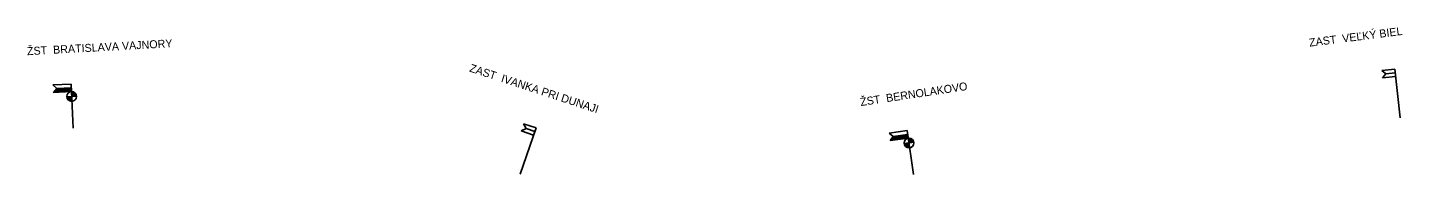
# Model space of a CAD drawing. Extents: x -566241 to -448637, y -1329577 to -1274522.
# Drawn here: x -566241 to -554213, y -1276346 to -1275058 of the extents above; entities that cross this region are included whole.
import ezdxf

# ---------------------------------------------------------------- set-up
doc = ezdxf.new("R2010")
doc.units = 0
doc.layers.add('DOPRAVNE', color=7, linetype='Continuous')
doc.layers.add('DOPRAVNE NAZOV', color=7, linetype='Continuous')

msp = doc.modelspace()

# ---------------------------------------------------------------- linework, layer by layer
at = {"layer": 'DOPRAVNE'}
for p, q in [((-554280, -1275422), (-554394, -1275435)), ((-554394, -1275435), (-554358, -1275464)), ((-554358, -1275464), (-554387, -1275500)), ((-554273, -1275488), (-554387, -1275500)), ((-554277, -1275455), (-554358, -1275464)), ((-554234, -1275848), (-554280, -1275422)), ((-565860, -1275553), (-566020, -1275561)), ((-566020, -1275561), (-565986, -1275593)), ((-565986, -1275593), (-566017, -1275627)), ((-565857, -1275619), (-566017, -1275627)), ((-566015, -1275627), (-565984, -1275592)), ((-566008, -1275627), (-565976, -1275592)), ((-566001, -1275626), (-565969, -1275592)), ((-565994, -1275626), (-565962, -1275591)), ((-565987, -1275626), (-565955, -1275591)), ((-565858, -1275586), (-565986, -1275593)), ((-565980, -1275625), (-565948, -1275591)), ((-565973, -1275625), (-565941, -1275590)), ((-565966, -1275625), (-565934, -1275590)), ((-565958, -1275624), (-565927, -1275590)), ((-565951, -1275624), (-565920, -1275589)), ((-565944, -1275624), (-565913, -1275589)), ((-565937, -1275623), (-565906, -1275589)), ((-565930, -1275623), (-565899, -1275588)), ((-565923, -1275623), (-565892, -1275588)), ((-565916, -1275622), (-565885, -1275588)), ((-565909, -1275622), (-565878, -1275587)), ((-565902, -1275622), (-565871, -1275587)), ((-565895, -1275621), (-565863, -1275587)), ((-565888, -1275621), (-565858, -1275588)), ((-565881, -1275621), (-565858, -1275596)), ((-565874, -1275620), (-565858, -1275603)), ((-565874, -1275620), (-565858, -1275603)), ((-565867, -1275620), (-565857, -1275610)), ((-565867, -1275620), (-565857, -1275610)), ((-565842, -1275941), (-565860, -1275553)), ((-565860, -1275620), (-565857, -1275617)), ((-565860, -1275620), (-565857, -1275617)), ((-565857, -1275624), (-565853, -1275619)), ((-565856, -1275631), (-565847, -1275620)), ((-565856, -1275638), (-565841, -1275622)), ((-565856, -1275645), (-565836, -1275624)), ((-565855, -1275652), (-565832, -1275626)), ((-565855, -1275659), (-565828, -1275629)), ((-565898, -1275664), (-565812, -1275660)), ((-565897, -1275669), (-565893, -1275664)), ((-565896, -1275675), (-565886, -1275664)), ((-565894, -1275680), (-565879, -1275664)), ((-565892, -1275685), (-565872, -1275663)), ((-565889, -1275689), (-565865, -1275663)), ((-565885, -1275693), (-565858, -1275663)), ((-565882, -1275696), (-565855, -1275666)), ((-565878, -1275699), (-565854, -1275673)), ((-565873, -1275701), (-565854, -1275680)), ((-565868, -1275703), (-565854, -1275687)), ((-565863, -1275705), (-565853, -1275694)), ((-565851, -1275662), (-565824, -1275632)), ((-565844, -1275662), (-565821, -1275636)), ((-565837, -1275662), (-565818, -1275640)), ((-565830, -1275661), (-565815, -1275645)), ((-565823, -1275661), (-565813, -1275651)), ((-561932, -1276343), (-561792, -1275938)), ((-561880, -1275943), (-561922, -1275963)), ((-561814, -1276001), (-561922, -1275963)), ((-561792, -1275938), (-561901, -1275901)), ((-561901, -1275901), (-561880, -1275943)), ((-561803, -1275970), (-561880, -1275943)), ((-558545, -1275961), (-558704, -1275984)), ((-558704, -1275984), (-558667, -1276012)), ((-558490, -1276346), (-558545, -1275961)), ((-558667, -1276012), (-558695, -1276049)), ((-558536, -1276026), (-558695, -1276049)), ((-558692, -1276049), (-558664, -1276012)), ((-558685, -1276048), (-558657, -1276011)), ((-558678, -1276047), (-558650, -1276010)), ((-558671, -1276046), (-558643, -1276009)), ((-558540, -1275994), (-558667, -1276012)), ((-558664, -1276045), (-558636, -1276008)), ((-558657, -1276044), (-558629, -1276007)), ((-558650, -1276043), (-558622, -1276006)), ((-558643, -1276042), (-558615, -1276005)), ((-558636, -1276041), (-558608, -1276004)), ((-558629, -1276040), (-558601, -1276003)), ((-558622, -1276039), (-558594, -1276002)), ((-558615, -1276038), (-558587, -1276001)), ((-558608, -1276037), (-558580, -1276000)), ((-558601, -1276036), (-558573, -1275998)), ((-558594, -1276035), (-558566, -1275997)), ((-558587, -1276034), (-558559, -1275996)), ((-558580, -1276033), (-558552, -1275995)), ((-558573, -1276032), (-558545, -1275994)), ((-558572, -1276075), (-558487, -1276063)), ((-558571, -1276079), (-558568, -1276075)), ((-558570, -1276085), (-558561, -1276074)), ((-558567, -1276090), (-558554, -1276073)), ((-558566, -1276031), (-558540, -1275996)), ((-558564, -1276095), (-558547, -1276072)), ((-558561, -1276099), (-558540, -1276071)), ((-558559, -1276030), (-558539, -1276003)), ((-558557, -1276102), (-558533, -1276070)), ((-558553, -1276105), (-558529, -1276073)), ((-558552, -1276029), (-558538, -1276010)), ((-558552, -1276029), (-558538, -1276010)), ((-558549, -1276108), (-558528, -1276080)), ((-558545, -1276028), (-558537, -1276017)), ((-558545, -1276028), (-558537, -1276017)), ((-558544, -1276110), (-558527, -1276087)), ((-558539, -1276111), (-558526, -1276094)), ((-558538, -1276027), (-558536, -1276024)), ((-558538, -1276027), (-558536, -1276024)), ((-558535, -1276031), (-558532, -1276026)), ((-558534, -1276038), (-558525, -1276026)), ((-558533, -1276045), (-558520, -1276027)), ((-558533, -1276112), (-558525, -1276101)), ((-558532, -1276052), (-558515, -1276029)), ((-558531, -1276059), (-558510, -1276031)), ((-558530, -1276066), (-558506, -1276033)), ((-558526, -1276069), (-558502, -1276036)), ((-558519, -1276068), (-558498, -1276040)), ((-558512, -1276067), (-558495, -1276044)), ((-558505, -1276066), (-558492, -1276048)), ((-558498, -1276065), (-558490, -1276053))]:
    msp.add_line(p, q, dxfattribs=at)
for centre in [(-565855, -1275662), (-558530, -1276069)]:
    msp.add_circle(centre, 43, dxfattribs=at)

# ---------------------------------------------------------------- texts
at = {"layer": 'DOPRAVNE NAZOV'}
for s, rotation, p in [('ZAST  VEĽKÝ BIEL', 7.2351, (-555025, -1275226)), ('ŽST  BRATISLAVA VAJNORY', 3.1788, (-566244, -1275301)), ('ZAST  IVANKA PRI DUNAJI', 341.8844, (-562381, -1275442)), ('ŽST  BERNOLAKOVO', 8.5991, (-558951, -1275746))]:
    msp.add_text(s, height=70, rotation=rotation, dxfattribs=at).set_placement(p)

doc.saveas('drawing.dxf')
